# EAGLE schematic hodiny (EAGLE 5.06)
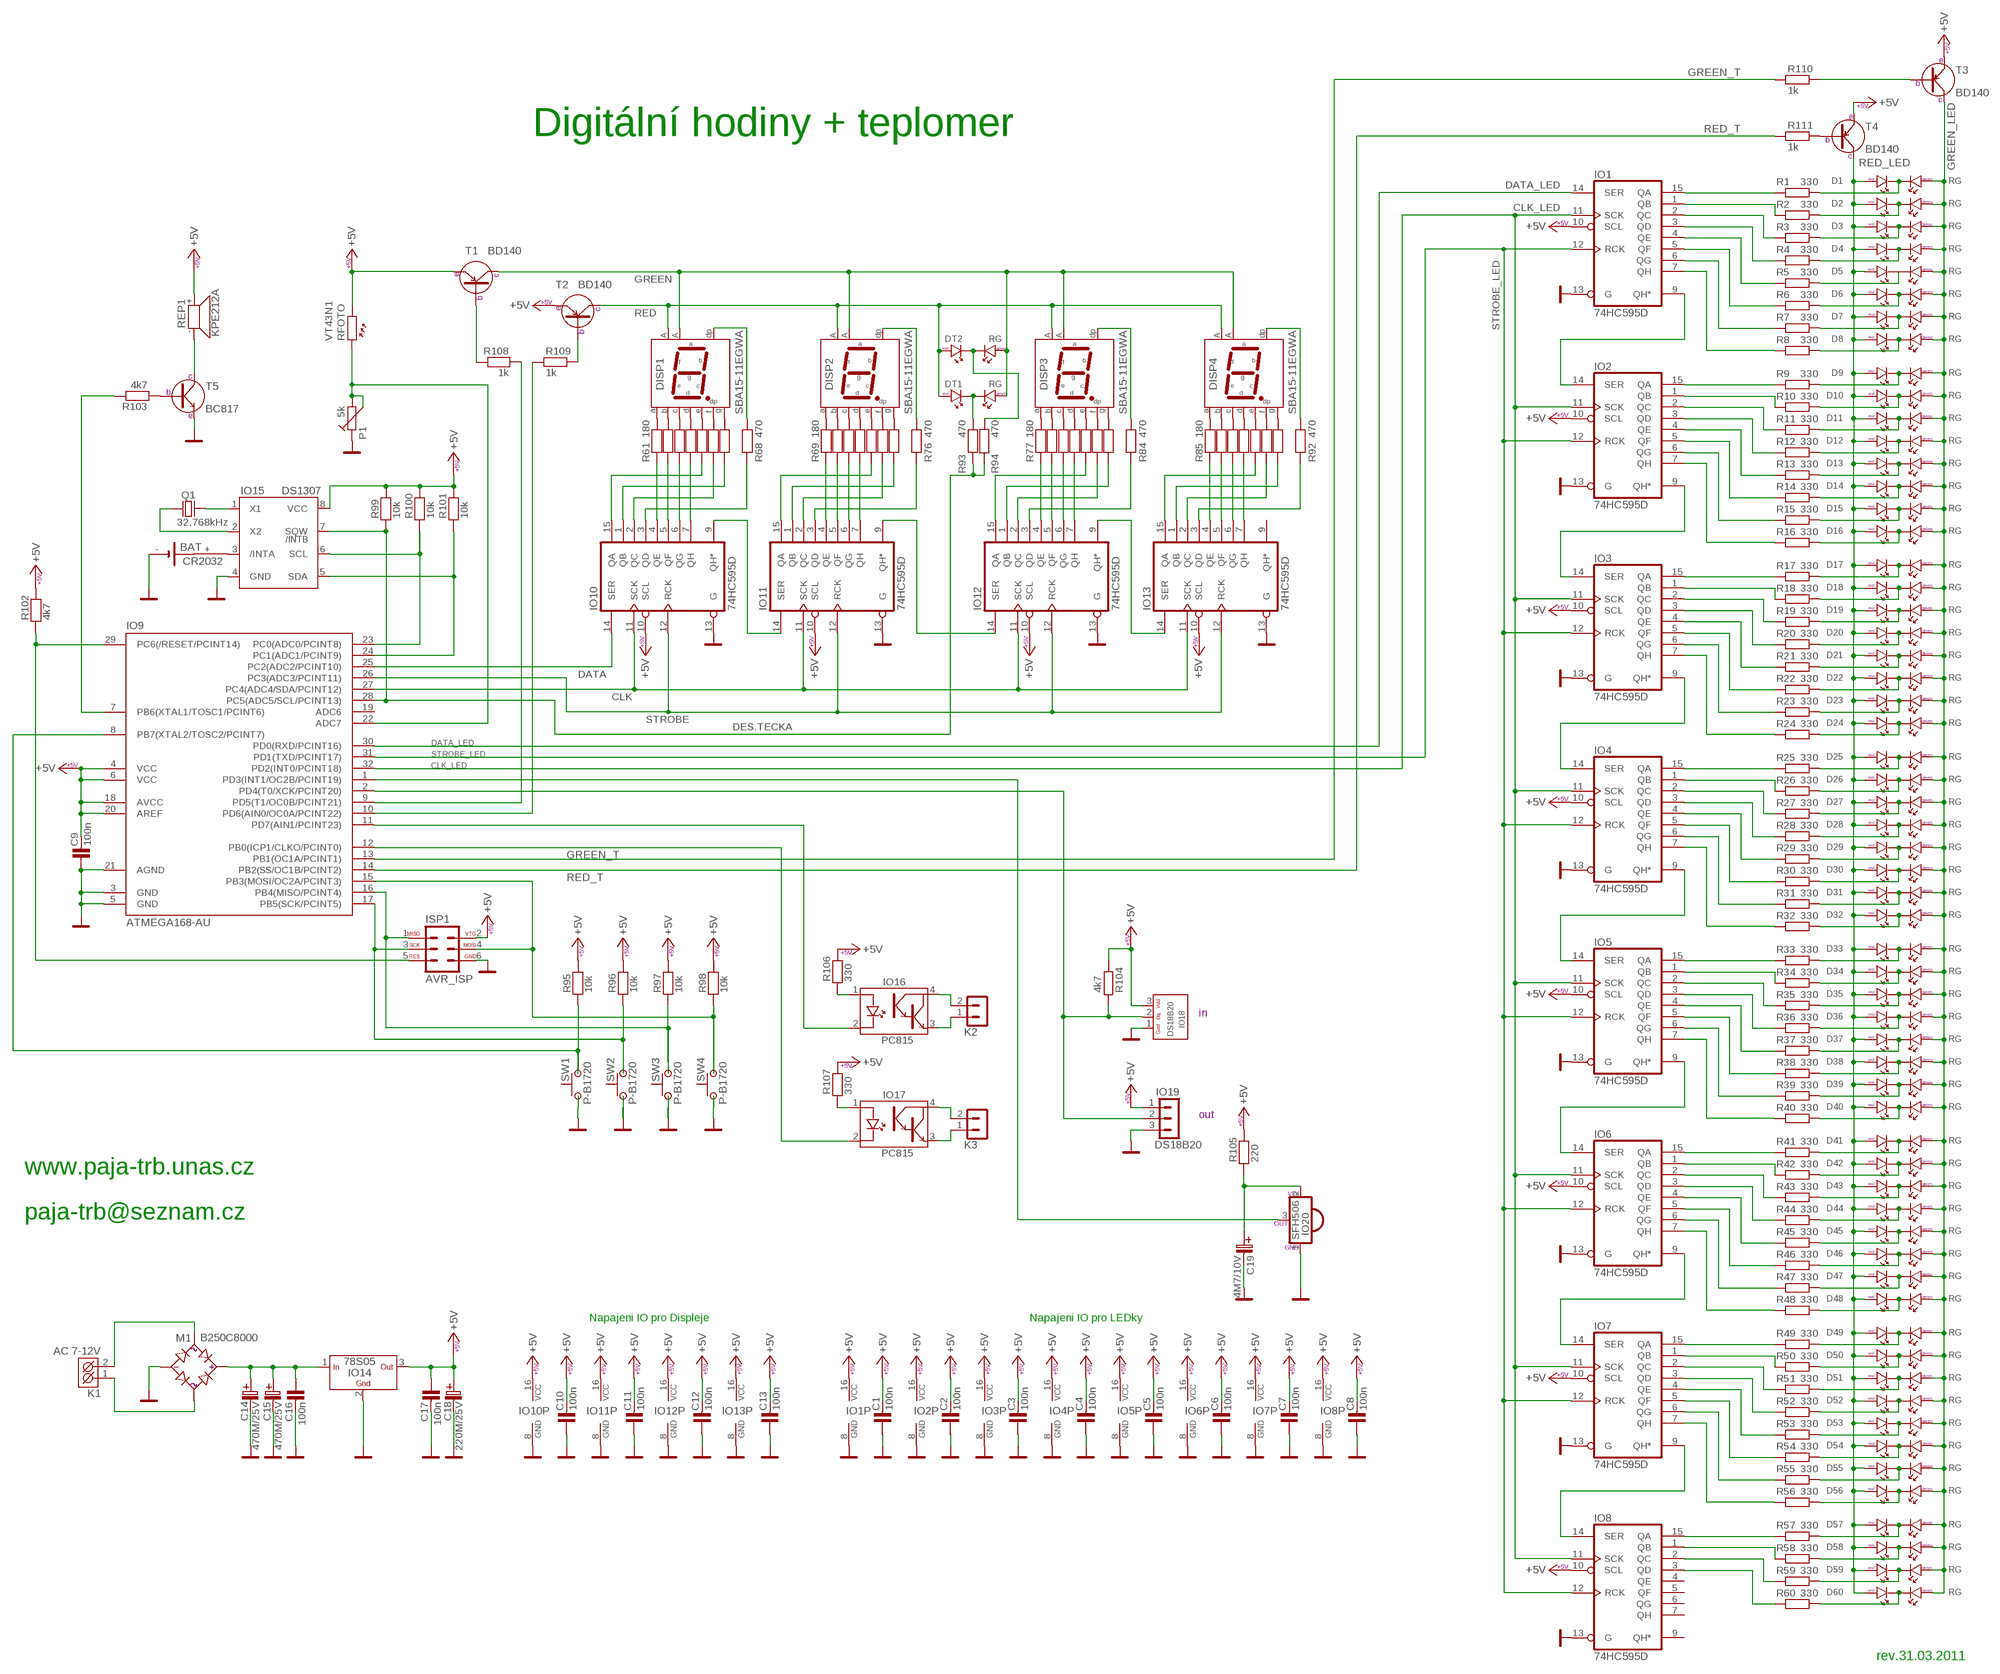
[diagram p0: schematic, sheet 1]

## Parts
BAT  CR2032  B2430UNI  [B2430UNI]
C1  100n  C-KERAMIK_SMD_1206  [1206]
C2  100n  C-KERAMIK_SMD_1206  [1206]
C3  100n  C-KERAMIK_SMD_1206  [1206]
C4  100n  C-KERAMIK_SMD_1206  [1206]
C5  100n  C-KERAMIK_SMD_1206  [1206]
C6  100n  C-KERAMIK_SMD_1206  [1206]
C7  100n  C-KERAMIK_SMD_1206  [1206]
C8  100n  C-KERAMIK_SMD_1206  [1206]
C9  100n  C-KERAMIK_SMD_1206  [1206]
C10  100n  C-KERAMIK_SMD_1206  [1206]
C11  100n  C-KERAMIK_SMD_1206  [1206]
C12  100n  C-KERAMIK_SMD_1206  [1206]
C13  100n  C-KERAMIK_SMD_1206  [1206]
C14  470M/25V  [C_EL_5]
C15  470M/25V  [C_EL_5]
C16  100n  C-KERAMIK_SMD_1206  [1206]
C17  100n  C-KERAMIK_SMD_1206  [1206]
C18  220M/25V  [C_EL_3,5]
C19  4M7/10V  4M7/20V  [B]
D1  RG  LED_DUO_5  [LED_5-DUO]
D2  RG  LED_DUO_5  [LED_5-DUO]
D3  RG  LED_DUO_5  [LED_5-DUO]
D4  RG  LED_DUO_5  [LED_5-DUO]
D5  RG  LED_DUO_5  [LED_5-DUO]
D6  RG  LED_DUO_5  [LED_5-DUO]
D7  RG  LED_DUO_5  [LED_5-DUO]
D8  RG  LED_DUO_5  [LED_5-DUO]
D9  RG  LED_DUO_5  [LED_5-DUO]
D10  RG  LED_DUO_5  [LED_5-DUO]
D11  RG  LED_DUO_5  [LED_5-DUO]
D12  RG  LED_DUO_5  [LED_5-DUO]
D13  RG  LED_DUO_5  [LED_5-DUO]
D14  RG  LED_DUO_5  [LED_5-DUO]
D15  RG  LED_DUO_5  [LED_5-DUO]
D16  RG  LED_DUO_5  [LED_5-DUO]
D17  RG  LED_DUO_5  [LED_5-DUO]
D18  RG  LED_DUO_5  [LED_5-DUO]
D19  RG  LED_DUO_5  [LED_5-DUO]
D20  RG  LED_DUO_5  [LED_5-DUO]
D21  RG  LED_DUO_5  [LED_5-DUO]
D22  RG  LED_DUO_5  [LED_5-DUO]
D23  RG  LED_DUO_5  [LED_5-DUO]
D24  RG  LED_DUO_5  [LED_5-DUO]
D25  RG  LED_DUO_5  [LED_5-DUO]
D26  RG  LED_DUO_5  [LED_5-DUO]
D27  RG  LED_DUO_5  [LED_5-DUO]
D28  RG  LED_DUO_5  [LED_5-DUO]
D29  RG  LED_DUO_5  [LED_5-DUO]
D30  RG  LED_DUO_5  [LED_5-DUO]
D31  RG  LED_DUO_5  [LED_5-DUO]
D32  RG  LED_DUO_5  [LED_5-DUO]
D33  RG  LED_DUO_5  [LED_5-DUO]
D34  RG  LED_DUO_5  [LED_5-DUO]
D35  RG  LED_DUO_5  [LED_5-DUO]
D36  RG  LED_DUO_5  [LED_5-DUO]
D37  RG  LED_DUO_5  [LED_5-DUO]
D38  RG  LED_DUO_5  [LED_5-DUO]
D39  RG  LED_DUO_5  [LED_5-DUO]
D40  RG  LED_DUO_5  [LED_5-DUO]
D41  RG  LED_DUO_5  [LED_5-DUO]
D42  RG  LED_DUO_5  [LED_5-DUO]
D43  RG  LED_DUO_5  [LED_5-DUO]
D44  RG  LED_DUO_5  [LED_5-DUO]
D45  RG  LED_DUO_5  [LED_5-DUO]
D46  RG  LED_DUO_5  [LED_5-DUO]
D47  RG  LED_DUO_5  [LED_5-DUO]
D48  RG  LED_DUO_5  [LED_5-DUO]
D49  RG  LED_DUO_5  [LED_5-DUO]
D50  RG  LED_DUO_5  [LED_5-DUO]
D51  RG  LED_DUO_5  [LED_5-DUO]
D52  RG  LED_DUO_5  [LED_5-DUO]
D53  RG  LED_DUO_5  [LED_5-DUO]
D54  RG  LED_DUO_5  [LED_5-DUO]
D55  RG  LED_DUO_5  [LED_5-DUO]
D56  RG  LED_DUO_5  [LED_5-DUO]
D57  RG  LED_DUO_5  [LED_5-DUO]
D58  RG  LED_DUO_5  [LED_5-DUO]
D59  RG  LED_DUO_5  [LED_5-DUO]
D60  RG  LED_DUO_5  [LED_5-DUO]
DISP1  SBA15-11EGWA  HD-AB5RD  [HD-AB]
DISP2  SBA15-11EGWA  HD-AB5RD  [HD-AB]
DISP3  SBA15-11EGWA  HD-AB5RD  [HD-AB]
DISP4  SBA15-11EGWA  HD-AB5RD  [HD-AB]
DT1  RG  LED_DUO_5  [LED_5-DUO]
DT2  RG  LED_DUO_5  [LED_5-DUO]
IO1  74HC595D  [SO16]
IO2  74HC595D  [SO16]
IO3  74HC595D  [SO16]
IO4  74HC595D  [SO16]
IO5  74HC595D  [SO16]
IO6  74HC595D  [SO16]
IO7  74HC595D  [SO16]
IO8  74HC595D  [SO16]
IO9  ATMEGA168-AU  ATMEGA48/88/168-AU  [TQFP32-08]
IO10  74HC595D  [SO16]
IO11  74HC595D  [SO16]
IO12  74HC595D  [SO16]
IO13  74HC595D  [SO16]
IO14  78S05  78_LEZ_LEZ  [TO-220]
IO15  DS1307  DS1337_SO8  [SO08]
IO16  PC815  [DIL4]
IO17  PC815  [DIL4]
IO18  DS18B20  DS18B20_TO-92  [TO-92]
IO19  DS18B20  PSH02-03P  [PSH02-03P]
IO20  SFH506  [SFH506]
ISP1  AVR_ISP  [MLW06G]
K1  AC 7-12V  ARK500/2  [ARK500/2]
K2  PSH02-02P  [PSH02-02P]
K3  PSH02-02P  [PSH02-02P]
M1  B250C8000  D-MUSTEK_B250C8000  [DM_KBU]
P1  5k  TRIMRPT6V  [PT6V]
Q1  32,768kHz  Q_3X8  [Q_3X8]
R1  330  R_SMD_1206  [1206]
R2  330  R_SMD_1206  [1206]
R3  330  R_SMD_1206  [1206]
R4  330  R_SMD_1206  [1206]
R5  330  R_SMD_1206  [1206]
R6  330  R_SMD_1206  [1206]
R7  330  R_SMD_1206  [1206]
R8  330  R_SMD_1206  [1206]
R9  330  R_SMD_1206  [1206]
R10  330  R_SMD_1206  [1206]
R11  330  R_SMD_1206  [1206]
R12  330  R_SMD_1206  [1206]
R13  330  R_SMD_1206  [1206]
R14  330  R_SMD_1206  [1206]
R15  330  R_SMD_1206  [1206]
R16  330  R_SMD_1206  [1206]
R17  330  R_SMD_1206  [1206]
R18  330  R_SMD_1206  [1206]
R19  330  R_SMD_1206  [1206]
R20  330  R_SMD_1206  [1206]
R21  330  R_SMD_1206  [1206]
R22  330  R_SMD_1206  [1206]
R23  330  R_SMD_1206  [1206]
R24  330  R_SMD_1206  [1206]
R25  330  R_SMD_1206  [1206]
R26  330  R_SMD_1206  [1206]
R27  330  R_SMD_1206  [1206]
R28  330  R_SMD_1206  [1206]
R29  330  R_SMD_1206  [1206]
R30  330  R_SMD_1206  [1206]
R31  330  R_SMD_1206  [1206]
R32  330  R_SMD_1206  [1206]
R33  330  R_SMD_1206  [1206]
R34  330  R_SMD_1206  [1206]
R35  330  R_SMD_1206  [1206]
R36  330  R_SMD_1206  [1206]
R37  330  R_SMD_1206  [1206]
R38  330  R_SMD_1206  [1206]
R39  330  R_SMD_1206  [1206]
R40  330  R_SMD_1206  [1206]
R41  330  R_SMD_1206  [1206]
R42  330  R_SMD_1206  [1206]
R43  330  R_SMD_1206  [1206]
R44  330  R_SMD_1206  [1206]
R45  330  R_SMD_1206  [1206]
R46  330  R_SMD_1206  [1206]
R47  330  R_SMD_1206  [1206]
R48  330  R_SMD_1206  [1206]
R49  330  R_SMD_1206  [1206]
R50  330  R_SMD_1206  [1206]
R51  330  R_SMD_1206  [1206]
R52  330  R_SMD_1206  [1206]
R53  330  R_SMD_1206  [1206]
R54  330  R_SMD_1206  [1206]
R55  330  R_SMD_1206  [1206]
R56  330  R_SMD_1206  [1206]
R57  330  R_SMD_1206  [1206]
R58  330  R_SMD_1206  [1206]
R59  330  R_SMD_1206  [1206]
R60  330  R_SMD_1206  [1206]
R61  180  R_SMD_1206  [1206]
R62  180  R_SMD_1206  [1206]
R63  180  R_12,7  [R-12,7]
R64  180  R_12,7  [R-12,7]
R65  180  R_7,5  [R-7,5]
R66  180  R_SMD_1206  [1206]
R67  180  R_SMD_1206  [1206]
R68  470  R_SMD_1206  [1206]
R69  180  R_SMD_1206  [1206]
R70  180  R_SMD_1206  [1206]
R71  180  R_12,7  [R-12,7]
R72  180  R_12,7  [R-12,7]
R73  180  R_7,5  [R-7,5]
R74  180  R_SMD_1206  [1206]
R75  180  R_SMD_1206  [1206]
R76  470  R_SMD_1206  [1206]
R77  180  R_SMD_1206  [1206]
R78  180  R_SMD_1206  [1206]
R79  180  R_12,7  [R-12,7]
R80  180  R_12,7  [R-12,7]
R81  180  R_7,5  [R-7,5]
R82  180  R_SMD_1206  [1206]
R83  180  R_SMD_1206  [1206]
R84  470  R_SMD_1206  [1206]
R85  180  R_SMD_1206  [1206]
R86  180  R_SMD_1206  [1206]
R87  180  R_7,5  [R-7,5]
R88  180  R_7,5  [R-7,5]
R89  180  R_7,5  [R-7,5]
R90  180  R_SMD_1206  [1206]
R91  180  R_SMD_1206  [1206]
R92  470  R_SMD_1206  [1206]
R93  470  R_12,7  [R-12,7]
R94  470  R_SMD_1206  [1206]
R95  10k  R_SMD_1206  [1206]
R96  10k  R_SMD_1206  [1206]
R97  10k  R_SMD_1206  [1206]
R98  10k  R_SMD_1206  [1206]
R99  10k  R_SMD_1206  [1206]
R100  10k  R_SMD_1206  [1206]
R101  10k  R_SMD_1206  [1206]
R102  4k7  R_SMD_1206  [1206]
R103  4k7  R_SMD_1206  [1206]
R104  4k7  R_SMD_1206  [1206]
R105  220  R_SMD_1206  [1206]
R106  330  R_SMD_1206  [1206]
R107  330  R_SMD_1206  [1206]
R108  1k  R_SMD_1206  [1206]
R109  1k  R_SMD_1206  [1206]
R110  1k  R_SMD_1206  [1206]
R111  1k  R_SMD_1206  [1206]
REP1  KPE212A  [KPE212A]
RFOTO  VT43N1  R-FOTO  [R-FOTO]
SW1  P-B1720  [P-B1720]
SW2  P-B1720  [P-B1720]
SW3  P-B1720  [P-B1720]
SW4  P-B1720  [P-B1720]
T1  BD140  BD140_LEZ  [TO-126]
T2  BD140  BD140_LEZ  [TO-126]
T3  BD140  BD140_LEZ  [TO-126]
T4  BD140  BD140_LEZ  [TO-126]
T5  BC817  [SOT-23]

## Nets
+5V: C1.2 C2.2 C3.2 C4.2 C5.2 C6.2 C7.2 C8.2 C9.2 C10.2 C11.2 C12.2 C13.2 C17.1 C18.C+(C_EL+) IO1.10(SCL) IO1.16(VCC) IO2.10(SCL) IO2.16(VCC) IO3.10(SCL) IO3.16(VCC) IO4.10(SCL) IO4.16(VCC) IO5.10(SCL) IO5.16(VCC) IO6.10(SCL) IO6.16(VCC) IO7.10(SCL) IO7.16(VCC) IO8.10(SCL) IO8.16(VCC) IO9.4(VCC) IO9.6(VCC) IO9.18(AVCC) IO9.20(AREF) IO10.10(SCL) IO10.16(VCC) IO11.10(SCL) IO11.16(VCC) IO12.10(SCL) IO12.16(VCC) IO13.10(SCL) IO13.16(VCC) IO14.3(OUT) IO15.8(VCC) IO18.3(+VCC) IO19.1 ISP1.2 R95.2 R96.2 R97.2 R98.2 R99.2 R100.2 R101.2 R102.2 R104.2 R105.2 R106.2 R107.2 REP1.+ RFOTO.2 T1.1(E) T2.1(E) T3.1(E) T4.1(E)
+BAT: BAT.+ IO15.3(/INTA)
+SFH: C19.+(C_EL+) IO20.2(VCC) R105.1
AC1: K1.2(K2) M1.AC1
AC2: K1.1(K1) M1.AC2
CLK: IO9.27(PC4(ADC4/SDA/PCINT12)) IO10.11(SCK) IO11.11(SCK) IO12.11(SCK) IO13.11(SCK)
CLK_LED: IO1.11(SCK) IO2.11(SCK) IO3.11(SCK) IO4.11(SCK) IO5.11(SCK) IO6.11(SCK) IO7.11(SCK) IO8.11(SCK) IO9.32(PD2(INT0/PCINT18))
DATA: IO9.25(PC2(ADC2/PCINT10)) IO10.14(SER)
DATA_IR: IO9.1(PD3(INT1/OC2B/PCINT19)) IO20.3(OUT)
DATA_LED: IO1.14(SER) IO9.30(PD0(RXD/PCINT16))
DES.TECKA: IO9.28(PC5(ADC5/SCL/PCINT13)) IO15.7(SQW) R93.1 R94.1 R99.1
GND: BAT.- C1.1 C2.1 C3.1 C4.1 C5.1 C6.1 C7.1 C8.1 C9.1 C10.1 C11.1 C12.1 C13.1 C14.C-(C_EL-) C15.C-(C_EL-) C16.2 C17.2 C18.C-(C_EL-) C19.-(C_EL-) IO1.8(GND) IO1.13(G) IO2.8(GND) IO2.13(G) IO3.8(GND) IO3.13(G) IO4.8(GND) IO4.13(G) IO5.8(GND) IO5.13(G) IO6.8(GND) IO6.13(G) IO7.8(GND) IO7.13(G) IO8.8(GND) IO8.13(G) IO9.3(GND) IO9.5(GND) IO9.21(AGND) IO10.8(GND) IO10.13(G) IO11.8(GND) IO11.13(G) IO12.8(GND) IO12.13(G) IO13.8(GND) IO13.13(G) IO14.2(GND) IO15.4(GND) IO18.1(GND) IO19.3 IO20.1(GND) ISP1.6 M1.- P1.1 SW1.1 SW1.3 SW2.1 SW2.3 SW3.1 SW3.3 SW4.1 SW4.3 T5.2(E)
GREEN: DISP1.5(CA2) DISP2.5(CA2) DISP3.5(CA2) DISP4.5(CA2) DT1.A2 DT2.A2 T1.2(C)
GREEN_LED: D1.A2 D2.A2 D3.A2 D4.A2 D5.A2 D6.A2 D7.A2 D8.A2 D9.A2 D10.A2 D11.A2 D12.A2 D13.A2 D14.A2 D15.A2 D16.A2 D17.A2 D18.A2 D19.A2 D20.A2 D21.A2 D22.A2 D23.A2 D24.A2 D25.A2 D26.A2 D27.A2 D28.A2 D29.A2 D30.A2 D31.A2 D32.A2 D33.A2 D34.A2 D35.A2 D36.A2 D37.A2 D38.A2 D39.A2 D40.A2 D41.A2 D42.A2 D43.A2 D44.A2 D45.A2 D46.A2 D47.A2 D48.A2 D49.A2 D50.A2 D51.A2 D52.A2 D53.A2 D54.A2 D55.A2 D56.A2 D57.A2 D58.A2 D59.A2 D60.A2 T3.2(C)
GREEN_T: IO9.13(PB1(OC1A/PCINT1)) R110.1
MISO: IO9.16(PB4(MISO/PCINT4)) ISP1.1 R97.1 SW3.2 SW3.4
MOSI: IO9.15(PB3(MOSI/OC2A/PCINT3)) ISP1.4 R98.1 SW4.2 SW4.4
N$1: D1.K R1.2
N$2: IO1.15(QA) R1.1
N$3: D2.K R2.2
N$4: IO1.1(QB) R2.1
N$5: DT1.K R93.2
N$6: DT2.K R94.2
N$7: IO4.15(QA) R25.1
N$8: D3.K R3.2
N$9: D4.K R4.2
N$10: D5.K R5.2
N$11: D6.K R6.2
N$12: IO10.9(QH*) IO11.14(SER)
N$13: IO11.9(QH*) IO12.14(SER)
N$14: IO1.2(QC) R3.1
N$15: IO1.3(QD) R4.1
N$16: IO1.4(QE) R5.1
N$17: IO1.5(QF) R6.1
N$18: IO1.6(QG) R7.1
N$19: IO1.7(QH) R8.1
N$20: IO2.15(QA) R9.1
N$21: IO2.1(QB) R10.1
N$22: IO10.1(QB) R67.1
N$23: IO10.2(QC) R66.1
N$24: IO10.4(QE) R61.1
N$25: IO10.5(QF) R62.1
N$26: IO10.15(QA) R65.1
N$27: IO10.6(QG) R63.1
N$28: IO10.7(QH) R64.1
N$29: IO10.3(QD) R68.1
N$30: IO11.3(QD) R76.1
N$31: IO11.1(QB) R75.1
N$32: IO11.2(QC) R74.1
N$33: IO11.4(QE) R69.1
N$34: IO11.5(QF) R70.1
N$35: IO11.15(QA) R73.1
N$36: IO11.6(QG) R71.1
N$37: IO11.7(QH) R72.1
N$38: D9.K R9.2
N$39: D10.K R10.2
N$40: D11.K R11.2
N$41: D12.K R12.2
N$42: D13.K R13.2
N$43: D14.K R14.2
N$44: IO12.9(QH*) IO13.14(SER)
N$45: D15.K R15.2
N$46: D16.K R16.2
N$47: DISP2.8(DP) R76.2
N$48: IO12.3(QD) R84.1
N$49: IO12.1(QB) R83.1
N$50: IO12.2(QC) R82.1
N$51: IO12.4(QE) R77.1
N$52: IO12.5(QF) R78.1
N$53: IO12.15(QA) R81.1
N$54: IO12.6(QG) R79.1
N$55: IO12.7(QH) R80.1
N$56: DISP3.8(DP) R84.2
N$57: IO13.3(QD) R92.1
N$58: IO13.1(QB) R91.1
N$59: IO13.2(QC) R90.1
N$60: IO13.4(QE) R85.1
N$61: IO13.5(QF) R86.1
N$62: IO13.15(QA) R89.1
N$63: R103.1 T5.1(B)
N$64: IO9.7(PB6(XTAL1/TOSC1/PCINT6)) R103.2
N$65: IO4.1(QB) R26.1
N$67: D25.K R25.2
N$68: D26.K R26.2
N$69: D27.K R27.2
N$70: D28.K R28.2
N$71: D7.K R7.2
N$72: IO9.22(ADC7) P1.2 P1.3 RFOTO.1
N$73: D29.K R29.2
N$74: D30.K R30.2
N$75: D31.K R31.2
N$76: D32.K R32.2
N$77: IO4.2(QC) R27.1
N$78: IO4.3(QD) R28.1
N$79: IO4.4(QE) R29.1
N$80: IO4.5(QF) R30.1
N$81: R109.2 T2.3(B)
N$82: D8.K R8.2
N$83: IO2.2(QC) R11.1
N$84: IO9.29(PC6(/RESET/PCINT14)) ISP1.5 R102.1
N$85: IO2.3(QD) R12.1
N$86: IO2.4(QE) R13.1
N$87: IO2.5(QF) R14.1
N$88: IO2.6(QG) R15.1
N$89: IO2.7(QH) R16.1
N$90: IO1.9(QH*) IO2.14(SER)
N$91: IO3.15(QA) R17.1
N$92: IO3.1(QB) R18.1
N$93: D17.K R17.2
N$94: D18.K R18.2
N$95: D19.K R19.2
N$96: D20.K R20.2
N$97: D21.K R21.2
N$98: D22.K R22.2
N$99: D23.K R23.2
N$100: D24.K R24.2
N$101: IO3.2(QC) R19.1
N$102: IO3.3(QD) R20.1
N$103: IO4.6(QG) R31.1
N$104: IO3.4(QE) R21.1
N$105: IO3.5(QF) R22.1
N$106: IO3.6(QG) R23.1
N$107: IO3.7(QH) R24.1
N$108: IO2.9(QH*) IO3.14(SER)
N$109: IO4.7(QH) R32.1
N$110: IO3.9(QH*) IO4.14(SER)
N$111: IO5.15(QA) R33.1
N$112: IO5.1(QB) R34.1
N$113: D33.K R33.2
N$114: D34.K R34.2
N$115: D35.K R35.2
N$116: D36.K R36.2
N$117: D37.K R37.2
N$118: D38.K R38.2
N$119: D39.K R39.2
N$120: D40.K R40.2
N$121: IO5.2(QC) R35.1
N$122: IO5.3(QD) R36.1
N$123: IO5.4(QE) R37.1
N$124: IO5.5(QF) R38.1
N$125: IO5.6(QG) R39.1
N$126: IO5.7(QH) R40.1
N$127: IO4.9(QH*) IO5.14(SER)
N$128: IO6.15(QA) R41.1
N$129: IO6.1(QB) R42.1
N$130: D41.K R41.2
N$131: D42.K R42.2
N$132: D43.K R43.2
N$133: D44.K R44.2
N$134: D45.K R45.2
N$135: D46.K R46.2
N$136: D47.K R47.2
N$137: D48.K R48.2
N$138: IO6.2(QC) R43.1
N$139: IO6.3(QD) R44.1
N$140: IO6.4(QE) R45.1
N$141: IO6.5(QF) R46.1
N$142: IO6.6(QG) R47.1
N$143: IO6.7(QH) R48.1
N$144: IO5.9(QH*) IO6.14(SER)
N$145: IO7.15(QA) R49.1
N$146: IO7.1(QB) R50.1
N$147: D49.K R49.2
N$148: D50.K R50.2
N$149: D51.K R51.2
N$150: D52.K R52.2
N$151: D53.K R53.2
N$152: D54.K R54.2
N$153: D55.K R55.2
N$154: D56.K R56.2
N$155: IO7.2(QC) R51.1
N$156: IO7.3(QD) R52.1
N$157: IO7.4(QE) R53.1
N$158: IO7.5(QF) R54.1
N$159: IO7.6(QG) R55.1
N$160: IO7.7(QH) R56.1
N$161: IO6.9(QH*) IO7.14(SER)
N$162: IO8.15(QA) R57.1
N$163: IO8.1(QB) R58.1
N$164: D57.K R57.2
N$165: D58.K R58.2
N$166: D59.K R59.2
N$167: D60.K R60.2
N$168: DISP1.7(A) R61.2
N$169: DISP1.6(B) R62.2
N$170: DISP1.4(C) R63.2
N$171: DISP1.3(D) R64.2
N$172: IO8.2(QC) R59.1
N$173: IO8.3(QD) R60.1
N$174: DISP1.2(E) R65.2
N$175: DISP1.9(F) R66.2
N$176: DISP1.10(G) R67.2
N$177: DISP1.8(DP) R68.2
N$178: IO7.9(QH*) IO8.14(SER)
N$179: IO13.6(QG) R87.1
N$180: IO13.7(QH) R88.1
N$181: DISP4.8(DP) R92.2
N$182: DISP2.7(A) R69.2
N$183: DISP2.6(B) R70.2
N$184: DISP2.4(C) R71.2
N$185: DISP2.3(D) R72.2
N$186: DISP2.2(E) R73.2
N$187: DISP2.9(F) R74.2
N$188: DISP2.10(G) R75.2
N$189: DISP3.7(A) R77.2
N$190: DISP3.6(B) R78.2
N$191: DISP3.4(C) R79.2
N$192: DISP3.3(D) R80.2
N$193: DISP3.2(E) R81.2
N$194: DISP3.9(F) R82.2
N$195: DISP3.10(G) R83.2
N$196: DISP4.7(A) R85.2
N$197: DISP4.6(B) R86.2
N$198: DISP4.4(C) R87.2
N$199: DISP4.3(D) R88.2
N$200: DISP4.2(E) R89.2
N$201: DISP4.9(F) R90.2
N$202: DISP4.10(G) R91.2
N$204: C14.C+(C_EL+) C15.C+(C_EL+) C16.1 IO14.1(IN) M1.+
N$205: IO9.10(PD6(AIN0/OC0A/PCINT22)) R109.1
N$206: R108.2 T1.3(B)
N$207: R111.2 T4.3(B)
N$208: IO9.9(PD5(T1/OC0B/PCINT21)) R108.1
N$209: R110.2 T3.3(B)
N$210: IO16.1(A) R106.1
N$212: IO16.4(C) K2.2
N$213: IO9.12(PB0(ICP1/CLKO/PCINT0)) IO17.2(K)
N$214: IO15.1(X1) Q1.2
N$215: IO15.2(X2) Q1.1
N$216: IO9.23(PC0(ADC0/PCINT8)) IO15.6(SCL) R100.1
N$217: IO9.24(PC1(ADC1/PCINT9)) IO15.5(SDA) R101.1
N$219: IO9.2(PD4(T0/XCK/PCINT20)) IO18.2(1WIRE) IO19.2 R104.1
N$221: IO16.3(E) K2.1
N$223: IO9.11(PD7(AIN1/PCINT23)) IO16.2(K)
N$224: IO17.1(A) R107.1
N$225: IO17.4(C) K3.2
N$226: IO17.3(E) K3.1
N$229: REP1.- T5.3(C)
RED: DISP1.1(CA1) DISP2.1(CA1) DISP3.1(CA1) DISP4.1(CA1) DT1.A1 DT2.A1 T2.2(C)
RED_LED: D1.A1 D2.A1 D3.A1 D4.A1 D5.A1 D6.A1 D7.A1 D8.A1 D9.A1 D10.A1 D11.A1 D12.A1 D13.A1 D14.A1 D15.A1 D16.A1 D17.A1 D18.A1 D19.A1 D20.A1 D21.A1 D22.A1 D23.A1 D24.A1 D25.A1 D26.A1 D27.A1 D28.A1 D29.A1 D30.A1 D31.A1 D32.A1 D33.A1 D34.A1 D35.A1 D36.A1 D37.A1 D38.A1 D39.A1 D40.A1 D41.A1 D42.A1 D43.A1 D44.A1 D45.A1 D46.A1 D47.A1 D48.A1 D49.A1 D50.A1 D51.A1 D52.A1 D53.A1 D54.A1 D55.A1 D56.A1 D57.A1 D58.A1 D59.A1 D60.A1 T4.2(C)
RED_T: IO9.14(PB2(SS/OC1B/PCINT2)) R111.1
SCK: IO9.17(PB5(SCK/PCINT5)) ISP1.3 R96.1 SW2.2 SW2.4
STROBE: IO9.26(PC3(ADC3/PCINT11)) IO10.12(RCK) IO11.12(RCK) IO12.12(RCK) IO13.12(RCK)
STROBE_LED: IO1.12(RCK) IO2.12(RCK) IO3.12(RCK) IO4.12(RCK) IO5.12(RCK) IO6.12(RCK) IO7.12(RCK) IO8.12(RCK) IO9.31(PD1(TXD/PCINT17))
TLAC1: IO9.8(PB7(XTAL2/TOSC2/PCINT7)) R95.1 SW1.2 SW1.4
Unconnected: BAT.+@1(+) BAT.+@2(+) BAT.+@3(+) BAT.+@4(+) BAT.-@1(-) IO8.4(QE) IO8.5(QF) IO8.6(QG) IO8.7(QH) IO8.9(QH*) IO9.19(ADC6) IO13.9(QH*)

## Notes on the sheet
- Digitální hodiny + teplomer
- in
- out
- www.paja-trb.unas.cz
- paja-trb@seznam.cz
- Napajeni IO pro Displeje | Napajeni IO pro LEDky
- rev.31.03.2011

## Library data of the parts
BAT = battery:B2430UNI: LI BATTERY
C1-C13 C16 C17 = #PaJa_23_e56:C-KERAMIK: Kondenzator - keramicky
C14 C15 = #PaJa_C-el_2:470M/25V
C18 = #PaJa_C-el_2:220M/25V
C19 = #PaJa_C-tantal_SMD:4M7/20V
D1-D60 DT1 DT2 = #PaJa_23_e56:LED_DUO: LED dioda - dvoubarevna - 3 vyvody, spol. Katoda
DISP1-DISP4 = #PaJa_23_e56:HD-AB5?RD: LED displej - SA - 38 mm - RG
IO1-IO8 IO10-IO13 = 74xx-eu:74*595: 8-bit SHIFT REGISTER, output latch
IO9 = atmega8:ATMEGA48/88/168
IO14 = #PaJa_23_e56:78??: Stabilizátor - 1A a 1,5A ?? - napeti => 05, 06, 08, 09, 12, 15, 18, 20, 24 => 1,5A ?? - napeti => 10, 12, 15, 18 => 1A S ?? - napeti => 05, 09, 10, 12, 15, 18, 24 => 2A T ?? - napeti => 05 => 3A
IO15 = #PaJa_23_e56:DS1337: RTC - obvod realneho casu
IO16 IO17 = #PaJa_23_e56:PC815: Optoclen
IO18 = #PaJa_23_e56:DS18B20: DS18B20 - teplomer, 1wire (-55 az 125°C)
IO19 = #PaJa_23_e56:PSH02-03: Konektory se zamkem - vidlice - 3pin
IO20 = #PaJa_23_e56:SFH506: Optoprijimac s tvarovacem - 36 kHz nebo 56 kHz
ISP1 = #PaJa_23_e56:AVR_ISP
K1 = #PaJa_23_e56:ARK500/2: Svorkovnice - roztec 5mm - dvojita
K2 K3 = #PaJa_23_e56:PSH02-02: Konektory se zamkem - vidlice - 2pin
M1 = #PaJa_23_e56:D-MUSTEK: Diodovy mustek - Graetz
P1 = #PaJa_23_e56:TRIMR: Trimr
Q1 = #PaJa_23_e56:Q_3X8: Krystal - 32,768kHz
R1-R111 = #PaJa_23_e56:R: Rezistor
REP1 = #PaJa_23_e56:KPE212A: Piezo-sirenka - 3V az 20V
RFOTO = #PaJa_23_e56:R-FOTO: Foto odpor
SW1-SW4 = #PaJa_23_e56:P-B1720: &micro;-tlacitko
T1-T4 = #PaJa_23_e56:BD140: Tranzistor PNP - Vykonovy - Ic=1,5A
T5 = #PaJa_23_e56:BC817: SMD tranzistor - NPN - ekv. BC337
